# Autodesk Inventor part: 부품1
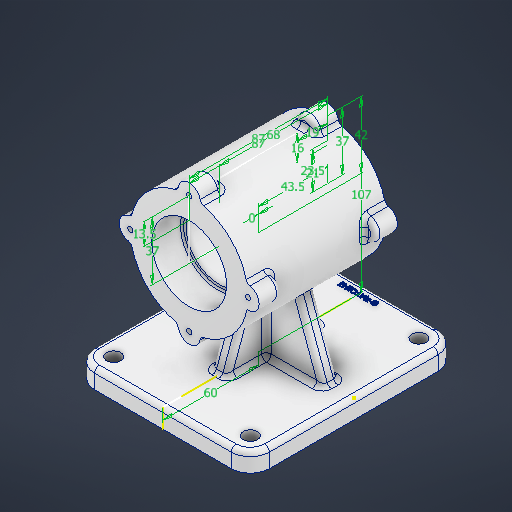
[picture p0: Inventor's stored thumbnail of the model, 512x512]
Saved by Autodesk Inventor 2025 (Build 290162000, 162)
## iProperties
Created: 2025-08
Part Number: 부품1
Material: 알루미늄 6061
Document SubType Name: Modeling
Designer: infra023
Density: 2.7 g/cm^3
Appearance: 알루미늄 - 평지
Mass: 1222.85 g
Surface Area: 802.911 cm^2
Volume: 452.907 cm^3
Author: infra023
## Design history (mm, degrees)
sketch "스케치1"
  geometry: L1 (55, 65)-(-55, 65); L2 (-55, 65)-(-55, -65); L3 (-55, -65)-(55, -65); L4 (55, -65)-(55, 65); 3 further points
  constraints: 8 end point, 2 midpoint, 2 parallel, 1 horizontal, 1 horizontal alignment, 1 perpendicular, 1 vertical alignment
  dimensions: "d0" = 130 distance of L3.end L1.start; "d1" = 110 distance of L2.end L3.end
extrude "돌출1" new body sketch "스케치1" distance "d2" = 12; taper "d3" = 0 deg
fillet "모깎기1" dims "d4" = 12
sketch "스케치2"
  geometry: L1 (43, 53)-(-43, 53); L2 (-43, 53)-(-43, -53); L3 (-43, -53)-(43, -53); L4 (43, -53)-(43, 53); 3 further points
  constraints: 8 end point, 2 midpoint, 2 parallel, 1 horizontal, 1 horizontal alignment, 1 perpendicular, 1 vertical alignment
  dimensions: "d5" = 106 distance of L1.end L2.end; "d6" = 86 distance of L2.end L3.end
hole "구멍1" sketch "스케치2" at (43, 53), (43, -53), (-43, -53), (-43, 53) diameter "d7" = 9; stored, may be unused: countersink angle "d11" = 90 deg, drill point angle "d13" = 118 deg; dims "d8" = 6, "d9" = 4, "d10" = 2, "d12" = 8
sketch "스케치3"
  geometry: L1 (-12, -53)-(-12, 53) reference; L2 (70, 5)-(70, -38.5); L3 (70, -38.5)-(107, -38.5); L4 (107, -38.5)-(107, 48.5); L5 (107, 48.5)-(70, 48.5); L6 (70, 5)-(70, 48.5); L7 (70, -38.5)-(91, -38.5); L8 (91, -19.5)-(91, 29.5); L9 (70, -38.5)-(93.5, -38.5); L10 (93.5, -38.5)-(93.5, -19.5); L11 (93.5, -19.5)-(70, -19.5); L12 (93.5, 48.5)-(93.5, 29.5); L13 (93.5, 29.5)-(70, 29.5); L14 (-12, 65)-(0, 65) reference; L15 (0, 65)-(0, 5); L16 (0, -53)-(0, 53) reference; L17 (0, 5)-(65, 5); 2 further points
  constraints: 28 end point, 6 perpendicular, 6 point on line, 3 parallel, 1 vertical
  dimensions: "d15" = 43.5 distance of L2.start L2.end; "d16" = 37 distance of L2.end L3.end; "d17" = 87 distance of L3.end L4.end; "d18" = 21 distance of L2.end L7.end; "d19" = 23.5 distance of L2.end L9.end; "d20" = 19 distance of L9.end L10.end; "d21" = 16 distance between parallel lines of L4 L8; "d112" = 60 distance of L14.end L15.end; "d114" = 13.5 distance between parallel lines of L12 L4; "d115" = 68 distance between parallel lines of L13 L3; "d117" = 87 distance from line of L12.start L3; "d118" = 37 distance from line of L13.end L4; "d119" = 42 distance from line of L17.end L4; "d120" = 0 vertical distance of L2.start L17.end; "d121" = 107 distance from line of L15.end L4
revolve "회전1" sketch "스케치3" stored, may be unused: angle "d22" = 90 deg
sketch "스케치4"
  geometry: L1 (0, 0)-(0, 37); L2 (0, 0)-(-37, 0); L3 (0, 0)-(37, 0); L4 (0, 0)-(0, -37); C1 r 21 at (0, 0) reference; C2 r 7 at (37, 0); C3 r 7 at (-37, 0); C4 r 7 at (0, 37); C5 r 7 at (0, -37); A1 r 37 centre (0, 0) between (0, 37) and (-37, 0) reference; 3 further points
  constraints: 8 end point, 4 centre point, 4 coincident, 4 point on circle, 2 horizontal, 2 vertical
  dimensions: "d23" = 14 diameter of C2; "d24" = 14 diameter of C3; "d25" = 14 diameter of C4; "d26" = 14 diameter of C5
sketch "스케치5"
  geometry: C1 r 7 at (0, 37) reference; C2 r 7 at (-37, 0) reference; C3 r 7 at (37, 0) reference; C4 r 7 at (0, -37) reference; 1 further point
extrude "돌출2" join sketch "스케치4" distance "d27" = 14; taper "d28" = 0 deg
extrude "돌출3" join sketch "스케치5" distance "d29" = 14; taper "d30" = 0 deg
fillet "모깎기2" dims "d31" = 3
fillet "모깎기3" dims "d32" = 3
fillet "모깎기4" dims "d33" = 3
sketch "스케치6"
  geometry: L1 (-37, -37)-(0, -37); C1 r 7 at (-37, -37); A1 r 7 centre (-37, -37) between (-38.239, -30.111) and (-38.239, -43.889) reference; A2 r 40 centre (0, -37) between (-39.905, -34.251) and (-39.905, -39.749) reference; 3 further points
  constraints: 2 end point, 1 centre point, 1 coincident, 1 concentric, 1 horizontal
extrude "돌출4" join sketch "스케치6" distance "d34" = 14; taper "d35" = 0 deg
fillet "모깎기5" dims "d36" = 3
sketch "스케치7"
  geometry: L1 (0, 37)-(-37, 37); L2 (0, 37)-(0, 74); L3 (0, 37)-(37, 37); L4 (0, 37)-(0, 0); C1 r 23.5 at (0, 37) reference; C2 r 37 at (0, 37); 1 further point
  constraints: 8 end point, 2 horizontal, 2 vertical, 1 centre point, 1 coincident
  dimensions: "d37" = 74 diameter of C2; "d38" = 37 distance of L1.start L1.end; "d39" = 37 distance of L1.start L2.end; "d40" = 37 distance of L1.start L3.end; "d41" = 37 distance of L1.start L4.end
hole "구멍2" sketch "스케치7" at (0, 74), (-37, 37), (37, 37), (0, 0) diameter "d42" = 3.242; stored, may be unused: countersink angle "d46" = 90 deg, drill point angle "d48" = 118 deg; dims "d43" = 8, "d44" = 4, "d45" = 2, "d47" = 10
sketch "스케치8"
  geometry: C1 r 1.621 at (0, 0) reference; C2 r 1.621 at (37, -37) reference; C3 r 1.621 at (-37, -37) reference; C4 r 1.621 at (0, -74) reference; 1 further point
hole "구멍3" sketch "스케치8" at (0, 0), (-37, -37), (37, -37), (0, -74) diameter "d49" = 3.242; stored, may be unused: countersink angle "d53" = 90 deg, drill point angle "d55" = 118 deg; dims "d50" = 8, "d51" = 4, "d52" = 2, "d54" = 10
sketch "스케치9"
  geometry: L1 (0, 0)-(0, 30); L2 (0, -53)-(0, 53) reference; L3 (0, 0)-(0, -30); L4 (0, 30)-(40, 15.441); L5 (0, 30)-(53.209, 30); L6 (0, -30)-(33, -17.989); L7 (0, -30)-(44.695, -30); L8 (0, 0)-(63, 0); L9 (33, -21.5)-(33, 31.5) reference; L10 (33, 5)-(33, 22); L11 (33, 5)-(33, -22.357); L12 (33, -17.989)-(40, -15.441); L13 (40, -15.441)-(40, 15.441); 1 further point
  constraints: 22 end point, 5 point on line, 3 horizontal, 1 midpoint, 1 vertical
  dimensions: "d56" = 30 distance of L1.start L1.end; "d57" = 30 distance of L1.start L3.end; "d58" = 20 deg angle of L4 L5; "d59" = 20 deg angle of L7 L6; "d71" = 70 deg angle of L12 L9; "d72" = 7 distance between parallel lines of L13 L9; "d73" = 30 distance from line of L8.end L9; "d74" = 37.57735 distance from line of L10.end L12; "d75" = 4.10424 distance from line of L11.end L12
sketch "스케치10"
  geometry: L1 (-43, -3)-(-55, -3) reference; L2 (-55, -3)-(-41, -3); L3 (43, -3)-(-43, -3) reference; L4 (-41, -3)-(-41, 0); L5 (-43, 0)-(-41, 0); L6 (-47.5, 0)-(-38.5, 0) reference; L7 (-41, 0)-(-24.257, 46); L8 (-41, 0)-(7.952, 0); L9 (43, -12)-(-43, -12) reference; L10 (0, 0)-(0, 49); L11 (55, -12)-(55, 0); L12 (55, -3)-(55, -12) reference; L13 (55, 0)-(41, 0); L14 (-41, 0)-(0, 0); L15 (41, 0)-(24.257, 46); 1 further point
  constraints: 20 end point, 2 collinear, 2 point on line, 1 equal length, 1 horizontal, 1 parallel, 1 perpendicular, 1 symmetric about line, 1 vertical, 1 vertical alignment, 1 other
  dimensions: "d62" = 14 distance of L1.end L2.end; "d63" = 70 deg angle of L8 L7; "d82" = 12 distance of L11.start L11.end; "d83" = 14 distance of L11.end L13.end; "d85" = 7.95218 distance from line of L8.end L10; "d86" = 20 deg angle of L10 L15
extrude "돌출6" join sketch "스케치9" stored distance "d76" = 10; taper "d77" = 0 deg
feature "리브2" dims "d87" = 1, "d88" = 10, "d89" = 0, "d90" = 0, "d91" = 1, "d92" = 1
sketch "스케치11"
  geometry: L1 (55, -3)-(55, -12) reference; L2 (55, -12)-(55, 0); L3 (-43, 0)-(43, 0) reference; L4 (41, 0)-(23.529, 48); 1 further point
  constraints: 4 end point, 1 collinear, 1 point on line
  dimensions: "d93" = 12 distance of L1.end L2.end; "d94" = 14 distance of L2.end L4.start; "d96" = 20 deg angle of L1 L4; "d97" = 31.47057 distance from line of L4.end L1
feature "리브3" sketch "스케치11" dims "d98" = 1, "d99" = 10, "d100" = 0, "d101" = 0, "d102" = 1, "d103" = 1
fillet "모깎기10" dims "d104" = 3
fillet "모깎기12" dims "d106" = 3
fillet "모깎기13" dims "d107" = 3
sketch "스케치12" dims "d0" = 130, "d1" = 110
  geometry: L1 (12.123, 56.285)-(-12.123, 56.285); L2 (-12.123, 56.285)-(-12.123, 59.715); L3 (-12.123, 59.715)-(12.123, 59.715); L4 (12.123, 59.715)-(12.123, 56.285); L5 (0, 0)-(0, 58); 2 further points
  constraints: 2 end point, 2 midpoint, 1 horizontal alignment, 1 vertical, 1 vertical alignment, 2 other
  dimensions: "d108" = 58 distance of L5.start L5.end
feature "엠보싱1" sketch "스케치12" dims "d0" = 130, "d1" = 110, "d109" = 0.5, "d110" = 0
fillet "모깎기14" dims "d111" = 1
sketch "스케치13"
  geometry: 1 further point
node "솔리드1"
feature "A9D066F2-1C7D-4E18-AEED-F7BC21143FA4" dims "d7" = 9, "d8" = 6, "d9" = 4, "d10" = 2, "d11" = 90 deg, "d12" = 8, "d13" = 118 deg
